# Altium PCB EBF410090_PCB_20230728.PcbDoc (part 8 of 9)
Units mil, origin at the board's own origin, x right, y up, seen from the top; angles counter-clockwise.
Board outline 5393.69 x 3858.26 mil, 6 copper layers (TOP, GND02, ART03, ART04, PWR05, BOTTOM), stack 47.2 mil thick; 570 components, 437 nets, 2015 pads, 1260 vias.
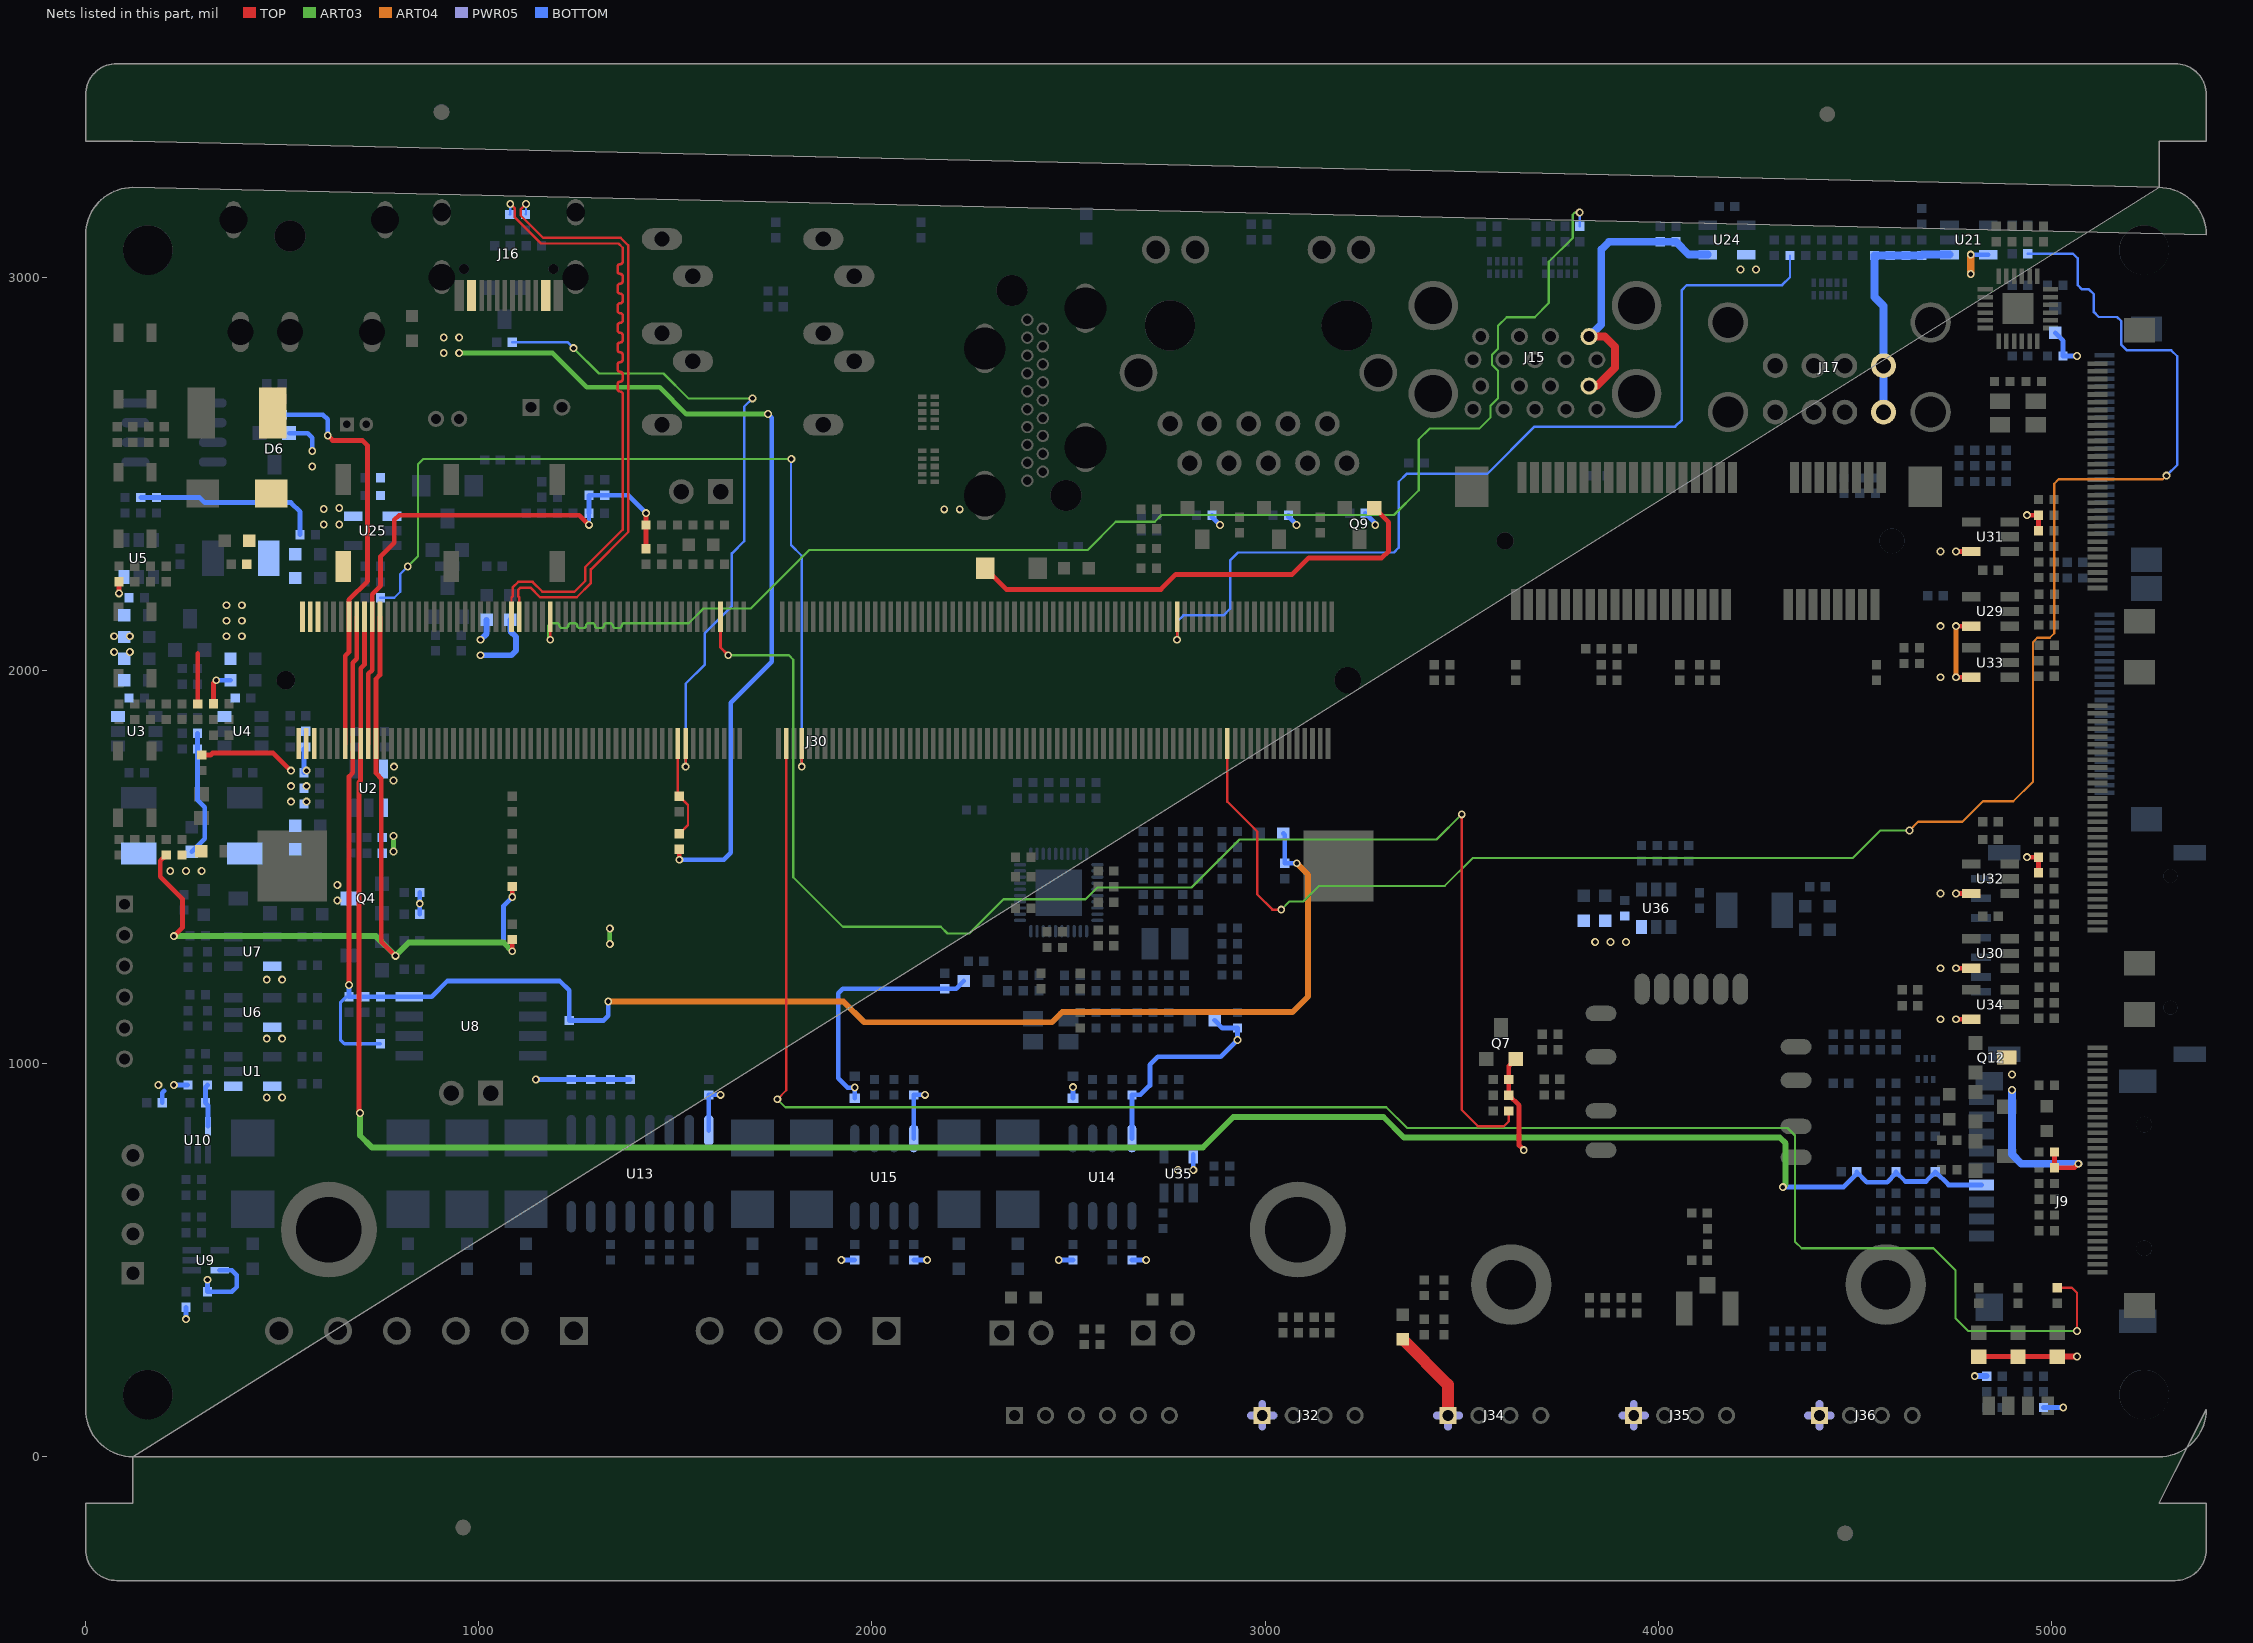
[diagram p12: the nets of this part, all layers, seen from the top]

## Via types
v1: diameter 20, hole 12, TOP to BOTTOM, 1260 vias

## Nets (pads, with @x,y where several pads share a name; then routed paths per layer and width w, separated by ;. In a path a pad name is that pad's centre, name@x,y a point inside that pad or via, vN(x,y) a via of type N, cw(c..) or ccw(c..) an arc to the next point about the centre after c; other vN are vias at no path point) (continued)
USB3_HOST1_SSTXP: C115.2 J30.195 | length 3556.1
  TOP w6.23: v1(1181.57,2078.07) J30.195@1181.57,2136.54
  ART03 w5.66: v1(1181.57,2078.07) 1176.4,2083.24 1176.4,2114.34 1182.06,2120 1198.89,2120 cw(c1198.89,2114) 1204.89,2114 ccw(c1210.89,2114) 1210.89,2108 1221.53,2108 ccw(c1221.53,2114) 1227.53,2114 cw(c1233.53,2114) 1233.53,2120 1244.17,2120 cw(c1244.17,2114) 1250.17,2114 ccw(c1256.17,2114) 1256.17,2108 1266.81,2108 ccw(c1266.81,2114) 1272.81,2114 cw(c1278.81,2114) 1278.81,2120 1289.45,2120 cw(c1289.45,2114) 1295.45,2114 ccw(c1301.45,2114) 1301.45,2108 1312.09,2108 ccw(c1312.09,2114) 1318.09,2114 cw(c1324.09,2114) 1324.09,2120 1334.73,2120 cw(c1334.73,2114) 1340.73,2114 ccw(c1346.73,2114) 1346.73,2108 1357.37,2108 ccw(c1357.37,2114) 1363.37,2114 cw(c1369.37,2114) 1369.37,2120 1533.99,2120 1571.33,2157.34 1691.33,2157.34 1839.99,2306 2548,2306 2620,2378 2719.01,2378 2736.35,2395.34 3327.66,2395.34 3390.66,2458.34 3390.66,2587.66 3418,2615 3545,2615 3573,2643 3573,2672.71 3592.64,2692.35 3592.64,2761.9 3577.05,2777.49 3577.05,2802.75 3592.64,2818.34 3592.64,2876.65 3614.33,2898.34 3685.66,2898.34 3721.66,2934.34 3721.66,3039.34 3782.33,3100.01 3782.33,3159.33 3788,3165 v1(3800,3165)
  BOTTOM w6.23: C115.2@3800,3129.68 v1(3800,3165)
USB20_HOST_PWR_EN: J30.28 R141.1 | length 4536.8
  TOP w6.16: J30.28@2904.02,1813.7 2904.02,1665.99 2980,1590.01 2980,1430 3018.42,1391.58 v1(3040.95,1391.58)
  ART03 w5.61: v1(3040.95,1391.58) 3061.37,1412 3097,1412 3137,1452 3457,1452 3528,1523 4495,1523 4565,1593 v1(4638.89,1593)
  ART04 w5.61: v1(4638.89,1593) 4660.89,1615 4774,1615 4826,1667 4903,1667 4953,1717 4953,2071.78 4964.22,2083 4995.78,2083 5007,2094.22 5007,2475 5018,2486 5283.56,2486 v1(5293,2495.44)
  BOTTOM w6.16: R141.1@4939.68,3060 5055,3060 5067,3048 5067,2980.16 5078.16,2969 5095.68,2969 5108,2956.68 5108,2911.32 5120.32,2899 5167,2899 5178,2888 5178,2828 5192,2814 5305,2814 5320,2799 5320,2522.44 v1(5293,2495.44)
USB20_OTG_PWR_EN: J30.138 R150.1 | length 2208
  TOP w6.16: v1(1821.34,1755.23) J30.138@1821.34,1813.7
  ART03 w5.61: v1(819.37,2264.37) 845,2290 845,2524 859,2538 v1(1795,2538)
  BOTTOM w6.16: R150.1@749.68,2185 785,2185 800,2200 800,2245 v1(819.37,2264.37) ; v1(1795,2538) 1794,2537 1794,2319 1821.34,2291.66 v1(1821.34,1755.23)
USB30_HOST_PWR_EN: J30.41 R147.1 | length 2445.4
  TOP w6.16: v1@2776.06,2078.09 J30.41@2776.06,2136.54
  BOTTOM w6.16: v1(2776.04,2078.07) 2776.04,2124.04 2792,2140 2894,2140 2911,2157 2911,2280 2931,2300 3327.68,2300 3340,2312.32 3340,2480 3360,2500 3565,2500 3685,2620 4042.68,2620 4060,2637.32 4060,2967.68 4072.32,2980 4315,2980 4335,3000 R147.1@4335,3055.32
"USB OTG": C125.1 C126.1 J16.A4 J16.A9 J16.B4 J16.B9 R149.1 U25.1 | length 2177.8
  TOP w12: v1(1510,1518.52) R149.1@1510,1545.32
  ART03 w12: v1(950,2807.26) 1187.74,2807.26 1275,2720 1460,2720 1528,2652 v1(1735.37,2652)
  BOTTOM w12: v1(1510,1518.52) 1623.52,1518.52 1641,1536 1641,1917.99 1745,2021.99 1745,2642.37 v1(1735.37,2652)
  other v1: 910.63,2807.26 910.63,2846.63 950,2846.63
USB_OTG0_DM: J30.203 R134.2 | length 1547.7
  TOP w6.23: J30.203@1102.83,2136.54 1102.83,2185.71 1100.1,2188.44 1100.1,2204.54 1106.33,2210.77 1131.11,2210.77 1155.88,2186 1248.99,2186 1285,2222.01 1285,2257.01 1380.23,2352.24 1380.23,3080.9 1361.02,3100.11 1163.89,3100.11 1106.11,3157.89 1106.11,3172.59 v1(1120,3186.48)
  BOTTOM w6.23: R134.2@1119,3159.68 1120,3160.68 v1(1120,3186.48)
USB_OTG0_DP: J30.205 R135.2 | length 1650.7
  TOP w6.23: v1(1080,3186.48) 1091.88,3174.6 1091.88,3151.99 1157.99,3085.88 1355.12,3085.88 1366,3075 1366,3039.89 cw(c1359.5,3039.89) 1359.5,3033.39 ccw(c1359.5,3026.89) 1353,3026.89 1353,3014.97 ccw(c1359.5,3014.97) 1359.5,3008.47 cw(c1359.5,3001.97) 1366,3001.97 1366,2990.05 cw(c1359.5,2990.05) 1359.5,2983.55 ccw(c1359.5,2977.05) 1353,2977.05 1353,2965.13 ccw(c1359.5,2965.13) 1359.5,2958.63 cw(c1359.5,2952.13) 1366,2952.13 1366,2940.21 cw(c1359.5,2940.21) 1359.5,2933.71 ccw(c1359.5,2927.21) 1353,2927.21 1353,2915.29 ccw(c1359.5,2915.29) 1359.5,2908.79 cw(c1359.5,2902.29) 1366,2902.29 1366,2890.37 cw(c1359.5,2890.37) 1359.5,2883.87 ccw(c1359.5,2877.37) 1353,2877.37 1353,2865.45 ccw(c1359.5,2865.45) 1359.5,2858.95 cw(c1359.5,2852.45) 1366,2852.45 1366,2840.53 cw(c1359.5,2840.53) 1359.5,2834.03 ccw(c1359.5,2827.53) 1353,2827.53 1353,2815.61 ccw(c1359.5,2815.61) 1359.5,2809.11 cw(c1359.5,2802.61) 1366,2802.61 1366,2790.69 cw(c1359.5,2790.69) 1359.5,2784.19 ccw(c1359.5,2777.69) 1353,2777.69 1353,2765.77 ccw(c1359.5,2765.77) 1359.5,2759.27 cw(c1359.5,2752.77) 1366,2752.77 1366,2740.85 cw(c1359.5,2740.85) 1359.5,2734.35 ccw(c1359.5,2727.85) 1353,2727.85 1353,2715.93 ccw(c1359.5,2715.93) 1359.5,2709.43 cw(c1359.5,2702.93) 1366,2702.93 1366,2358.14 1270.77,2262.91 1270.77,2227.91 1243.09,2200.23 1161.78,2200.23 1137.01,2225 1100.43,2225 1085.87,2210.44 1085.87,2188.44 1083.15,2185.72 J30.205@1083.15,2136.54
  BOTTOM w6.23: R135.2@1079,3159.68 1080,3160.68 v1(1080,3186.48)
USB_OTG0_ID: J30.160 R138.2 | length 1736.2
  TOP w6.16: v1(1526.05,1755.23) J30.160@1526.05,1813.7
  ART03 w5.61: v1(1241,2819.68) 1305.68,2755 1470,2755 1533,2692 v1(1696,2692)
  BOTTOM w6.16: R138.2@1084.68,2835 1225.68,2835 v1(1241,2819.68) ; v1(1526.05,1755.23) 1526.05,1966.05 1575,2015 1575,2095 1643.76,2163.76 1643.76,2297.76 1675,2329 1675,2671 v1(1696,2692)
USB_OTG0_VBUSDET: J30.162 R149.2 R151.1 | length 248.7
  TOP w6.16: J30.162@1506.37,1813.7 1506.37,1683.31 R151.1@1510,1679.68 1532,1657.68 1532,1606.68 R149.2@1510,1584.68
USER_LED: J30.142 R45.2 | length 4845.8
  TOP w6.16: v1(1759.37,909.37) 1781.97,931.97 J30.142@1781.97,1813.7 ; R45.2@5015,429.68 5052.32,429.68 5065,417 v1(5065,319.49)
  ART03 w5.61: v1(1759.37,909.37) 1779.74,889 3308.47,889 3361.47,836 4328.99,836 4348,816.99 4348,546.99 4364.99,530 4699.99,530 4756,473.99 4756,352.47 4788.98,319.49 v1(5065,319.49)
VCC3V3_SD: C54.1 C73.1 C74.1 J9.4 J30.243 J30.244 | length 5723.6
  TOP w12: v1(697.95,874.05) 695,877 695,1715 699.28,1719.28 J30.244@699.28,1813.7 700,1814.42 700,2005 709.13,2014.13 J30.243@709.13,2136.54
  ART03 w15: v1(697.95,874.05) 697.95,817.01 727.96,787 2842,787 2919,864 3301,864 3353,812 4309,812 4324,797 4324,692.74 v1(4316.89,685.63)
  BOTTOM w12: v1(4316.89,685.63) 4317.26,686 4471,686 4504.68,719.68 C54.1@4504.68,724.2 ; C54.1@4504.68,725 C54.1@4504.68,724.2 ; C73.1@4604.68,725 C73.1@4604.68,724.2 ; J9.4@4822.41,691.34 4738.34,691.34 C74.1@4704.68,725 4704.68,723.78 4680.9,700 4628.88,700 C73.1@4604.68,724.2 ; C54.1@4504.68,724.2 4530.88,698 4582,698 4604.68,720.68 C73.1@4604.68,724.2
VCC3V3_SYS: C8.1 C15.1 C16.1 C17.1 L1.2 R4.1 U1.5 U6.5 U31.5 U32.5 U35.5 | length 440.4
  TOP w12: v1(4757.19,1432.6) U32.5@4795.79,1432.6 ; v1(4757.19,2302.6) U31.5@4795.79,2302.6
  ART04 w12: v1(499.8,913.42) v1@500,913.22
  BOTTOM w12: C15.1@270,1538.5 303,1571.5 303,1652 284.68,1670.32 C8.1@284.68,1800 R4.1@284.68,1840 ; v1(2817.4,729.02) U35.5@2817.4,769.21
  other v1: 2778.03,729.02 460.43,913.42 460.43,1063.42 499.8,1063.42 4717.82,1432.6 215,1490 255,1490 295,1490 4717.82,2302.6
VCC5V0_SYS: C20.1 C24.1 C25.1 C26.1 C50.1 C51.1 J30.255 J30.256 J30.257 J30.258 J30.259 J30.260 L2.2 R11.1 R16.1 U2.5 U29.5 U30.5 U33.5 U34.5 | length 638.9
  TOP w12: R16.1@295,1784.68 317.8,1784.68 322.8,1789.68 477.44,1789.68 v1(522.12,1745) ; v1(4757.19,1112.6) U34.5@4795.79,1112.6 ; v1(4757.19,1242.6) U30.5@4795.79,1242.6 ; v1(4757.19,1982.6) U33.5@4795.79,1982.6 ; v1(4757.19,2112.6) U29.5@4795.79,2112.6
  ART04 w12: v1(4757.19,1982.6) v1(4757.19,2112.6)
  BOTTOM w12: C51.1@555.32,1740 555.32,1800.64 C20.1@559.68,1805 R11.1@559.68,1845
  other v1: 4717.82,1112.6 4717.82,1242.6 522.12,1666.26 561.49,1666.26 522.12,1705.63 561.49,1705.63 783.12,1720 561.49,1745 784.2,1755.23 4717.82,1982.6 4717.82,2112.6
VCC5V0_SYS_2: C29.1 C34.1 C35.1 C36.1 L3.2 R10.1 R20.1 U7.5 U21.5 U24.5 U25.5 | length 629.4
  ART04 w20: v1(4795,3008.23) v1(4795,3057.6)
  BOTTOM w12: R20.1@140,2439.68 C29.1@180,2439.68 290.32,2439.68 303,2427 522,2427 545.32,2403.68 C36.1@545.32,2345 ; v1(4795,3057.6) U21.5@4839.21,3057.6
  BOTTOM w15: v1(1004.41,2078.07) 1020,2093.66 R10.1@1020,2128.5
  other v1: 460.43,1213.42 499.8,1213.42 605.63,2371.15 645,2371.15 605.63,2410.52 645,2412.95 4209.37,3020 4248.74,3020
VCC5V0_USB20_HOST: C112.1 C113.1 C116.1 C117.1 J17.1 J17.7 U21.1 | length 599.5
  BOTTOM w20: J17.1@4572.9,2657.04 J17.7@4572.9,2775.15 4572.9,2927.1 4550,2950 C113.1@4550,3055.32 C112.1@4590,3055.32 C117.1@4630,3055.32 C116.1@4670,3055.32 4672.28,3057.6 U21.1@4740.79,3057.6
VCC5V0_USB30_HOST: C122.1 C123.1 J15.1 J15.10 U24.1 | length 741.7
  TOP w20: J15.10@3824.08,2723.19 3843.19,2723.19 3890,2770 3890,2823.14 3863.97,2849.17 J15.1@3824.08,2849.17
  BOTTOM w20: J15.1@3824.08,2849.17 3855,2880.09 3855,3070.32 3875,3090.32 C123.1@4005,3090.32 C122.1@4045,3090.32 4077.72,3057.6 U24.1@4125.79,3057.6
VCC_1V8: C52.1 C57.1 C58.1 C105.1 J30.245 J30.246 L7.2 R37.1 R38.1 U8.8 | length 4294.9
  TOP w12: v1(670,1200) 670,1730 679.6,1739.6 J30.246@679.6,1813.7 679.6,2019.6 689.45,2029.45 J30.245@689.45,2136.54
  ART04 w15: v1(1329.2,1157.93) 1927.07,1157.93 1980,1105 2458,1105 2484,1131 3070,1131 3109.5,1170.5 3109.5,1480.5 v1(3080.32,1509.68)
  BOTTOM w8: C52.1@670,1169.68 662.68,1169.68 648,1155 648,1060.32 658,1050.32 R38.1@750,1050.32
  BOTTOM w12: v1(670,1200) C52.1@670,1169.68 C57.1@710,1169.68 C58.1@750,1169.68 822.2,1169.68 U8.8@822.52,1170 880,1170 920,1210 1206,1210 1230,1186 R37.1@1230,1109.68 1317.19,1109.68 1329.2,1121.69 v1(1329.2,1157.93) ; L7.2@3046.5,1585 3050,1581.5 C105.1@3050,1509.68 v1(3080.32,1509.68)
VCC_12V: C1.1 C2.1 C3.1 C12.1 C13.1 C14.1 C21.1 C22.1 C23.1 C31.1 C32.1 C33.1 C38.1 C165.1 C170.1 C171.1 C172.1 D1.2 F1.2 Q4.3 Q12.3 R7.1 R9.1 R14.1 R23.1 R27.1 R196.1 U3.3 U4.3 U5.3 U36.3 | length 939.3
  TOP w12: v1(85,2196) R23.1@85,2225.32 ; R7.1@285,1914.68 285,2043 ; R14.1@325.32,1915 325.32,1968.24 v1(332.08,1975) ; C165.1@5007.68,775 R196.1@5007.68,735 5058.47,735 v1(5068.63,745.16)
  BOTTOM w12: v1(332.08,1975) C22.1@368.5,1975 ; R27.1@849.68,1380 v1(849.68,1406.8) C38.1@849.68,1435
  BOTTOM w15: v1(1004.41,2038.7) 1082.99,2038.7 1095,2050.71 1095,2085 1080,2100 R9.1@1080,2128.5
  BOTTOM w20: v1(4899.64,932.95) 4899.64,769.16 4923.64,745.16 v1(5068.63,745.16)
  other v1: 4899.64,972.32 3839.37,1309 3878.74,1309 3918.11,1309 640.23,1415.04 640.23,1454.41 72.37,2046.88 112.37,2046.88 72.37,2086.88 112.37,2086.88 357.96,2086.88 397.33,2086.88 357.96,2126.25 397.33,2126.25 357.96,2165.62 397.33,2165.62
VCC_RTC: J30.247 J30.248 R51.2 | length 1055.4
  TOP w12: v1(615.63,2597.37) 628,2585 704,2585 717,2572 717,2227 669.76,2179.76 J30.247@669.76,2136.54 669.76,2046.76 659.91,2036.91 J30.248@659.91,1813.7
  BOTTOM w12: R51.2@500,2650.32 603.62,2650.32 615.63,2638.31 v1(615.63,2597.37)
VCCA_1V8: C53.1 J30.239 J30.240 R35.1 R239.2 | length 2248.8
  TOP w12: R239.2@205,1530.32 190,1515.32 190,1475 246.21,1418.79 246.21,1346.05 v1(224.21,1324.05) ; J30.239@748.5,2136.54 748.5,1988.5 738.65,1978.65 J30.240@738.65,1813.7 738.65,1738.35 752,1725 752,1309.87 v1(787.87,1274) ; v1(1085,1285.85) C53.1@1085,1315.32 ; v1(1085,1423.52) R35.1@1085,1450.32
  ART03 w15: v1(224.21,1324.05) 737.82,1324.05 v1(787.87,1274) 821.87,1308 1062.85,1308 v1(1085,1285.85)
  BOTTOM w12: v1(1085,1285.85) 1063,1307.85 1063,1401.52 v1(1085,1423.52)
VCCIO_ACODEC: C55.1 C186.1 C191.1 J30.241 J30.242 R215.1 R217.1 | length 1436.8
  TOP w12: J30.242@718.97,1813.7 718.97,1990.97 728.82,2000.82 J30.241@728.82,2136.54 728.82,2193.82 750,2215 750,2290 785,2325 785,2383 797,2395 1255.32,2395 v1(1280,2370.32) ; R215.1@1425,2309.68 1425.32,2310 C186.1@1425.32,2370 v1(1425.32,2400)
  BOTTOM w10: v1(1280,2370.32) C55.1@1280,2400.32
  BOTTOM w12: C55.1@1280.32,2400 1280,2400.32 C191.1@1280,2445.32 R217.1@1320,2445.32 1380,2445.32 v1(1425.32,2400)
VDD_3V3: C5.1 C6.1 C59.1 C62.1 C69.1 C75.1 C76.1 C90.1 C94.1 C109.1 C127.1 C431.1 D6.2 D19.2 D20.2 J32.1 J34.1 J35.1 J36.1 L5.2 L6.2 LED1.2 LED2.2 LED3.2 Q7.2 R39.1 R42.1 R44.1 R47.2 R52.1 R53.1 R54.1 R55.1 R67.1 R68.1 R69.1 R70.1 R127.1 R152.1 R156.1 R157.1 R159.1 R164.1 R166.1 R168.1 R170.1 U1.1 U9.5 U10.5 U13.16 U14.8 U15.8 | length 3988.6
  TOP w12: Q7.2@3637.5,1011.5 3619.68,993.68 C109.1@3619.68,959.44 R127.1@3619.68,919.44 3620.26,919.44 3646,893.7 3646,791.72 v1(3657.89,779.83) ; LED3.2@4815,254.68 LED2.2@4915,254.68 LED1.2@5015,254.68 ; v1(4938,1525) R170.1@4967.32,1525 R166.1@4967.32,1485 ; v1(4938,2395) R168.1@4967.32,2395 R164.1@4967.32,2355
  TOP w15: LED1.2@5015,254.68 v1(5065,254.68)
  TOP w30: C431.1@3350,298.5 3465.08,183.42 J34.1@3465.08,105.01
  PWR05 w20: J32.1@2963.96,105.01 J32.1@2992.64,105.01 ; J32.1@2992.64,76.33 J32.1@2992.64,105.01 ; J32.1@2992.64,133.69 J32.1@2992.64,105.01 ; J32.1@3021.32,105.01 J32.1@2992.64,105.01 ; J34.1@3436.4,105.01 J34.1@3465.08,105.01 ; J34.1@3465.08,76.33 J34.1@3465.08,105.01 ; J34.1@3465.08,133.69 J34.1@3465.08,105.01 ; J34.1@3493.76,105.01 J34.1@3465.08,105.01 ; J35.1@3908.84,105.01 J35.1@3937.52,105.01 ; J35.1@3937.52,76.33 J35.1@3937.52,105.01 ; J35.1@3937.52,133.69 J35.1@3937.52,105.01 ; J35.1@3966.2,105.01 J35.1@3937.52,105.01 ; J36.1@4381.28,105.01 J36.1@4409.96,105.01 ; J36.1@4409.96,76.33 J36.1@4409.96,105.01 ; J36.1@4409.96,133.69 J36.1@4409.96,105.01 ; J36.1@4438.64,105.01 J36.1@4409.96,105.01
  BOTTOM w12: R42.1@194.68,900 194.68,925.46 199.61,930.39 ; v1(224.21,945.32) C6.1@260,945.32 ; v1(255,350) R39.1@255,380.32 ; v1(310,450) C59.1@310,419.68 372.09,419.68 384.09,431.68 384.09,462.09 372.09,474.09 U9.5@340.43,474.09 ; C5.1@310,945.32 304.68,940 C62.1@304.68,900 310.9,893.78 U10.5@310.9,840.43 ; D6.2@517.5,2603.5 564.26,2603.5 576.26,2591.5 v1(576.26,2558) ; v1(1145,959.68) R52.1@1235,959.68 R53.1@1285,959.68 R55.1@1335,959.68 R54.1@1385,959.68 ; U13.16@1584.8,829.8 1584.8,920.12 C69.1@1585,920.32 v1(1614.68,920.32) ; v1(1922.12,500.32) R68.1@1956.22,500.32 ; D20.2@1956.22,912.05 v1@1956.22,938.77 ; v1@1956.21,938.78 v1(1956.21,938.86) 1956.13,938.78 1938,938.78 1914,962.78 1914,1178.32 1926,1190.32 C94.1@2185,1190.32 2213.82,1190.32 L6.2@2233.5,1210 ; R70.1@2106.22,500.32 v1(2140.32,500.32) ; U15.8@2106.22,809.5 C76.1@2106.22,920.32 v1(2135,920.32) ; v1(2475,500.32) R67.1@2511.22,500.32 ; D19.2@2511.22,912.05 v1(2511.22,940) ; R69.1@2661.22,500.32 v1(2697.44,500.32) ; U14.8@2661.22,809.5 C75.1@2661.22,920.32 2683,920.32 2707,944.32 2707,997 2727,1017 2887,1017 v1(2930,1060) C90.1@2930,1090.32 2891.18,1090.32 L5.2@2871.5,1110 ; R159.1@2864.68,2395 2864.68,2390.32 v1(2885,2370) ; R157.1@3059.68,2395 3059.68,2390.32 v1(3080,2370) ; R156.1@3254.68,2400 3280,2374.68 v1(3280,2370) ; R44.1@4979.68,125 v1(5030,125) ; R152.1@5010,2858.5 5029.68,2838.82 C127.1@5029.68,2800 v1(5065,2800)
  BOTTOM w15: v1(4805,205) R47.2@4835.32,205
  other v1: 184.84,945.32 576.26,2518.63
VDD_5V: C10.1 C11.1 D27.2 Q9.1 U2.1 | length 1332.2
  TOP w12: D27.2@2288.07,2260 2342.07,2206 2735,2206 2773,2244 3069,2244 3111.02,2286.02 3297.02,2286.02 3314,2303 3314,2377 Q9.1@3277.5,2413.5
  ART03 w12: v1(782.71,1539.37) v1(782.71,1578.74) ; v1(1333.26,1304.37) v1(1333.26,1343.74)
  ART04 w12: v1(1333.26,1304.37) v1(1333.26,1343.74)
  other v1: 2184,2409.63 2223.37,2409.63
WLAN_PWR_EN: J30.151 R128.1 | length 3634.8
  TOP w6.16: v1(3500,1633.92) 3500,881.84 3541.16,840.68 3607.36,840.68 3619.68,853 R128.1@3619.68,879.44
  TOP w7.03: J30.151@1614.65,2136.54 1614.65,2058.38 v1(1634.33,2038.7)
  ART03 w5.61: v1(1634.33,2038.7) 1788.78,2038.7 1800,2027.48 1800,1474 1925.97,1348.03 2174.97,1348.03 2192,1331 2247.23,1331 2334.42,1418.19 2543.19,1418.19 2573,1448 2813,1448 2935,1570 3436.08,1570 v1(3500,1633.92)
pads on no net: H1.1 H2.1 H3.1 H4.1 J1. J6.1 J9. J14. J15.14 J15.15 J15.17 J15.18 J16. J16.A8 J16.B8 J20.13 J20.14 J21.13 J21.14 J21.16 J21.17 J21.18 J21.19 J21.20 J21.21 J22.1 J22.14 J22.24 J22.25 J22.30 J24. J24.3 J24.5 J24.6 J24.16 J24.17 J24.19 J24.28 J24.30 J24.32 J24.42 J24.44 J24.45 J24.46 J24.47 J24.48 J24.49 J24.51 J30. J30.19 J30.21 J30.27 J30.29 J30.32 J30.51 J30.65 J30.67 J30.69 J30.71 J30.73 J30.75 J30.96 J30.153 J30.213 J30.215 J30.217 J30.219 MARK.1 U12.1 U12.2 U17.3 U17.4 U17.9 U17.10 U17.11 U17.12 U17.13 U17.14 U22.2 U22.13 U22.17 U22.19 U22.21 U22.22 U22.23 U22.24 U26. U26.14 U37. U37.4 U37.6 U38.3

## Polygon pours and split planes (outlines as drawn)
GND on ART04 "ART04-GND" (solid, pour order 107): 82 vertices, not listed, extent 3318,1765 4067,2601
VCC_12V on ART04 "ART04-VCC_12V" (solid, pour order 109): 51 vertices, not listed, extent 348,691 4936,2300
VCC5V0_SYS_2 on ART04 "ART04-VCC5V0_SYS_2" (solid, pour order 110): 80 vertices, not listed, extent 180,1009 4816,3037
VDD_5V on ART04 "ART04-VDD_5V" (solid, pour order 104): 1273,1281 1260,1294 1260,2555 1270,2565 2220,2565 2235,2550 2235,2397 2210,2372 1423,2372 1403,2352 1403,1300 1384,1281 1273,1281
VCC3V3_SYS on ART04 "ART04-VCC3V3_SYS" (solid, pour order 111): 65 vertices, not listed, extent 180,397 5117,2400
GND on ART04 "ART04-GND 1" (solid, pour order 105): 82 vertices, not listed, extent 1423,1285 1894,2353
GND on ART04 "ART04-GND 2" (solid, pour order 117): 84 vertices, not listed, extent 20.01,20.01 5373.68,3208.33
VCC5V0_SYS on ART04 "ART04-VCC5V0_SYS" (solid, pour order 108): 50 vertices, not listed, extent 514,876 4776,2131
3V3_EDP on ART04 "ART04-3V3_EDP" (solid, pour order 106): 23 vertices, not listed, extent 2261,122 5241,707
GND on BOTTOM "BOTTOM-GND" (solid, pour order 74): 409,1918 409,2046 425,2062 425,2130 425,2132 430,2137 517,2137 525,2129 525,1926 517,1918 409,1918
GND on BOTTOM "BOTTOM-GND 1" (solid, pour order 84): 572,2358 572,2207 560,2195 436,2195 425,2184 425,2113 431,2107 631,2107 640,2116 640,2349 631,2358 572,2358
N28501 on BOTTOM "BOTTOM-N28501" (solid, pour order 13): 159,2350 253,2350 259,2344 259,2302 255,2298 225,2298 221,2302 221,2311 217,2315 159,2315 159,2350
N17592125 on BOTTOM "BOTTOM-N17592125" (solid, pour order 4): 4019,1460 4111,1460 4117,1454 4117,1423 4021,1423 4019,1425 4019,1460
"USB OTG" on BOTTOM "BOTTOM-USB OTG" (solid, pour order 90): 17 vertices, not listed, extent 738,2381 960,2857
GND on BOTTOM "BOTTOM-GND 2" (solid, pour order 78): 82 vertices, not listed, extent 4862,434 4958,713
GND on BOTTOM "BOTTOM-GND 3" (solid, pour order 67): 82 vertices, not listed, extent 1001,2434 1158,2548
GND on BOTTOM "BOTTOM-GND 4" (solid, pour order 68): 82 vertices, not listed, extent 276,1707 374,1892
5V0_CAM_1 on BOTTOM "BOTTOM-5V0_CAM_1" (solid, pour order 34): 5160,2394 5160,2341 5153,2334 5032,2334 5025,2341 5025,2388 5032,2395 5159,2395 5160,2394
GND on BOTTOM "BOTTOM-GND 5" (solid, pour order 102): 70 vertices, not listed, extent 4391,1274 4723,1986
GND on BOTTOM "BOTTOM-GND 6" (solid, pour order 82): 115 vertices, not listed, extent 485,2430 722,2573
VCC5V0_SYS_2 on BOTTOM "BOTTOM-VCC5V0_SYS_2" (solid, pour order 85): 19 vertices, not listed, extent 437,2219 704,2422
1V05_PHY on BOTTOM "BOTTOM-1V05_PHY" (solid, pour order 43): 2663,1213 2809,1213 2814,1218 2814,1338 2807,1345 2761,1345 2761,1251 2754,1244 2669,1244 2663,1238 2663,1213
GND on BOTTOM "BOTTOM-GND 7" (solid, pour order 75): 5003,2995 5003,2788 4927,2788 4927,2853 4915,2865 4868,2865 4861,2872 4861,2972 4884,2995 5003,2995
GND on BOTTOM "BOTTOM-GND 8" (solid, pour order 65): 82 vertices, not listed, extent 360,760 490,890
VCC_12V on BOTTOM "BOTTOM-VCC_12V" (solid, pour order 63): 82 vertices, not listed, extent 3793,1298 3972,1389
GND on BOTTOM "BOTTOM-GND 9" (solid, pour order 45): 82 vertices, not listed, extent 3785,1399 3932,1475
VCC5V0_SYS on BOTTOM "BOTTOM-VCC5V0_SYS" (solid, pour order 72): 358,1507 558,1507 568,1517 568,1747 558,1757 516,1757 506,1747 506,1572 496,1562 358,1562 358,1507
N17423580 on BOTTOM "BOTTOM-N17423580" (solid, pour order 49): 21 vertices, not listed, extent 335,1649 450,1860
3V3_EDP on BOTTOM "BOTTOM-3V3_EDP" (solid, pour order 79): 2805,705 2805,645 2885,645 2895,635 2895,360 2900,355 2950,355 2955,360 2955,700 2945,710 2810,710 2805,705
VCC_12V on BOTTOM "BOTTOM-VCC_12V 1" (solid, pour order 17): 82 vertices, not listed, extent 630,1400 700,1465
VDD_3V3 on BOTTOM "BOTTOM-VDD_3V3" (solid, pour order 30): 500,2622 579,2622 586,2615 586,2516 579,2509 544,2509 537,2516 537,2574 525,2586 500,2586 500,2622
5V0_CAM_2 on BOTTOM "BOTTOM-5V0_CAM_2" (solid, pour order 87): 5110,1734 5110,1160 5094,1144 5034,1144 5024,1134 5024,1107 5034,1097 5134,1097 5161,1124 5161,1734 5110,1734
GND on BOTTOM "BOTTOM-GND 10" (solid, pour order 44): 287,1588 287,1644 275,1656 275,1766 268,1773 199,1773 197,1771 197,1717 209,1705 228,1705 231,1702 231,1594 237,1588 287,1588
VCC5V0_SYS_2 on BOTTOM "BOTTOM-VCC5V0_SYS_2 1" (solid, pour order 15): 82 vertices, not listed, extent 445,1200 515,1265
GND on BOTTOM "BOTTOM-GND 11" (solid, pour order 66): 578,1519 578,1747 588,1757 642,1757 651,1748 651,1523 647,1519 578,1519
GND on BOTTOM "BOTTOM-GND 12" (solid, pour order 113): 205 vertices, not listed, extent 20.01,20.01 5373.68,3208.33
GND on BOTTOM "BOTTOM-GND 13" (solid, pour order 60): 5171,2680 5171,2766 5161,2776 5064,2776 5047,2793 5047,2848 5064,2865 5154,2865 5170,2849 5170,2827 5210,2787 5210,2680 5202,2672 5179,2672 5171,2680
GND on BOTTOM "BOTTOM-GND 14" (solid, pour order 89): 82 vertices, not listed, extent 1625,755 1920,880
GND on BOTTOM "BOTTOM-GND 15" (solid, pour order 88): 82 vertices, not listed, extent 2150,755 2445,880
GND on BOTTOM "BOTTOM-GND 16" (solid, pour order 62): 82 vertices, not listed, extent 3960,1254 4095,1373
VCC3V3_SYS on BOTTOM "BOTTOM-VCC3V3_SYS" (solid, pour order 14): 82 vertices, not listed, extent 445,1045 515,1110
N17759502 on BOTTOM "BOTTOM-N17759502" (solid, pour order 52): 20 vertices, not listed, extent 312,2453 498,2549
N03641 on BOTTOM "BOTTOM-N03641" (solid, pour order 48): 21 vertices, not listed, extent 65,1649 180,1860
VCC_12V on BOTTOM "BOTTOM-VCC_12V 2" (solid, pour order 59): 335,1869 385,1869 392,1876 392,2062 407,2077 407,2131 408,2132 408,2172 403,2177 355,2177 348,2170 348,2131 348,1909 335,1896 335,1869
N28533 on BOTTOM "BOTTOM-N28533" (solid, pour order 53): 21 vertices, not listed, extent 121,2220 351,2330
VDD_5V on BOTTOM "BOTTOM-VDD_5V" (solid, pour order 35): 82 vertices, not listed, extent 741,1517 793,1678
GND on BOTTOM "BOTTOM-GND 17" (solid, pour order 83): 18 vertices, not listed, extent 139,1917 256,2262
GND on BOTTOM "BOTTOM-GND 18" (solid, pour order 64): 82 vertices, not listed, extent 2510,2230 2670,2335
N17423559 on BOTTOM "BOTTOM-N17423559" (solid, pour order 5): 465,1734 465,1822 430,1822 430,1767 430,1755 427,1752 413,1752 413,1728 459,1728 465,1734
GND on BOTTOM "BOTTOM-GND 19" (solid, pour order 32): 82 vertices, not listed, extent 2840,718 2939,798
VDD_3V3 on BOTTOM "BOTTOM-VDD_3V3 1" (solid, pour order 40): 82 vertices, not listed, extent 175,920 405,960
GND on BOTTOM "BOTTOM-GND 20" (solid, pour order 20): 82 vertices, not listed, extent 811,2418 873,2500
MINIPCIE_3V3 on BOTTOM "BOTTOM-MINIPCIE_3V3" (solid, pour order 96): 21 vertices, not listed, extent 4288,1325 4397,1954
N17592129 on BOTTOM "BOTTOM-N17592129" (solid, pour order 56): 17 vertices, not listed, extent 3981,1330 4201,1435
VCC3V3_SYS on BOTTOM "BOTTOM-VCC3V3_SYS 1" (solid, pour order 22): 82 vertices, not listed, extent 2766,718 2834,798
VCC5V0_SYS on BOTTOM "BOTTOM-VCC5V0_SYS 1" (solid, pour order 3): 82 vertices, not listed, extent 742,1709 795,1776
GND on BOTTOM "BOTTOM-GND 21" (solid, pour order 86): 82 vertices, not listed, extent 2725,512 2910,694
GND on BOTTOM "BOTTOM-GND 22" (solid, pour order 73): 82 vertices, not listed, extent 4783,923 4949,1066
N17466585 on BOTTOM "BOTTOM-N17466585" (solid, pour order 36): 2730,1346 2623,1346 2604,1365 2595,1365 2595,1308 2602,1301 2669,1301 2675,1295 2675,1272 2682,1265 2730,1265 2730,1346
HDMI_5V on BOTTOM "BOTTOM-HDMI_5V" (solid, pour order 55): 2423,2230 2490,2230 2498,2238 2498,2382 2459,2421 2425,2421 2415,2411 2415,2238 2423,2230
VCC_12V on BOTTOM "BOTTOM-VCC_12V 3" (solid, pour order 71): 65,1869 101,1869 101,1911 108,1918 121,1918 122,1918 122,2201 111,2212 111,2255 66,2255 57,2246 57,1877 65,1869
GND on BOTTOM "BOTTOM-GND 23" (solid, pour order 24): 82 vertices, not listed, extent 730,2335 872,2375
GND on BOTTOM "BOTTOM-GND 24" (solid, pour order 94): 82 vertices, not listed, extent 745,763 1193,884
N03633 on BOTTOM "BOTTOM-N03633" (solid, pour order 6): 195,1734 195,1822 160,1822 160,1767 160,1755 157,1752 138,1752 138,1728 189,1728 195,1734
VCC5V0_SYS_2 on BOTTOM "BOTTOM-VCC5V0_SYS_2 2" (solid, pour order 16): 82 vertices, not listed, extent 4195,3005 4260,3075
VCC3V3_SYS on BOTTOM "BOTTOM-VCC3V3_SYS 2" (solid, pour order 69): 90,1563 297,1563 310,1550 310,1480 307,1477 99,1477 90,1486 90,1563
VCC3V3_SYS on BOTTOM "BOTTOM-VCC3V3_SYS 3" (solid, pour order 18): 82 vertices, not listed, extent 445,895 515,960
VCC5V0_SYS_2 on BOTTOM "BOTTOM-VCC5V0_SYS_2 3" (solid, pour order 25): 82 vertices, not listed, extent 4784,2997 4864,3073
3V3_AVDD_PHY on BOTTOM "BOTTOM-3V3_AVDD_PHY" (solid, pour order 23): 2273,1272 2351,1272 2357,1266 2357,1213 2320,1213 2312,1205 2312,1194 2280,1194 2280,1238 2273,1245 2273,1272
GND on BOTTOM "BOTTOM-GND 25" (solid, pour order 33): 82 vertices, not listed, extent 5022,2113 5102,2216
12V_EDP on TOP "TOP-12V_EDP" (solid, pour order 47): 4861,872 5030,872 5039,881 5039,1020 5032,1027 5001,1027 4994,1020 4994,925 4978,909 4861,909 4861,872
5V0_CAM_2 on TOP "TOP-5V0_CAM_2" (solid, pour order 31): 82 vertices, not listed, extent 4868,1094 5086,1128
HDMI_5V on TOP "TOP-HDMI_5V" (solid, pour order 41): 82 vertices, not listed, extent 2395,2220 2510,2300
GND on TOP "TOP-GND" (solid, pour order 114): 161 vertices, not listed, extent 20.01,20.01 5373.68,3208.33
N02088 on TOP "TOP-N02088" (solid, pour order 92): 248,2587 248,2893 267,2912 403,2912 421,2894 421,2776 403,2758 354,2758 339,2743 339,2589 339,2587 330,2578 257,2578 248,2587
VCC3V3_SYS on TOP "TOP-VCC3V3_SYS" (solid, pour order 29): 205,1505 205,1485 210,1480 305,1480 310,1485 310,1560 275,1560 260,1545 230,1545 225,1540 225,1515 220,1510 210,1510 205,1505
GND on TOP "TOP-GND 1" (solid, pour order 46): 82 vertices, not listed, extent 2530,2230 2695,2300
VCC3V3_SYS on TOP "TOP-VCC3V3_SYS 1" (solid, pour order 8): 82 vertices, not listed, extent 4705,2284 4825,2318
GND on TOP "TOP-GND 2" (solid, pour order 26): 82 vertices, not listed, extent 2581,1774 2638,1888
GND on TOP "TOP-GND 3" (solid, pour order 42): 82 vertices, not listed, extent 4945,793 5080,866
GND on TOP "TOP-GND 4" (solid, pour order 100): 4025,890 4025,350 4041,334 4213,334 4230,351 4230,700 4245,715 4430,715 4445,730 4445,910 4045,910 4025,890
VCC_12V on TOP "TOP-VCC_12V" (solid, pour order 28): 82 vertices, not listed, extent 4857,921 4915,1036
VCC5V0_SYS on TOP "TOP-VCC5V0_SYS" (solid, pour order 7): 82 vertices, not listed, extent 4705,1094 4825,1128
GND on TOP "TOP-GND 5" (solid, pour order 81): 22 vertices, not listed, extent 575,1695 656,2215
GND on TOP "TOP-GND 6" (solid, pour order 103): 62 vertices, not listed, extent 4384,1585 5150,2391
GND on TOP "TOP-GND 7" (solid, pour order 91): 2587,1502 2587,1125 2581,1119 2483,1119 2470,1132 2470,1349 2506,1385 2506,1516 2513,1523 2566,1523 2587,1502
GND on TOP "TOP-GND 8" (solid, pour order 50): 82 vertices, not listed, extent 604,2441 705,2568
GND on TOP "TOP-GND 9" (solid, pour order 70): 49 vertices, not listed, extent 1188,2791 1313,2990
VCC3V3_SYS on TOP "TOP-VCC3V3_SYS 2" (solid, pour order 9): 82 vertices, not listed, extent 4705,1414 4825,1448
GND on TOP "TOP-GND 10" (solid, pour order 95): 250,2525 393,2525 408,2510 408,2412 382,2386 382,2258 315,2258 309,2264 309,2300 294,2315 156,2315 154,2317 154,2518 161,2525 250,2525
VCC5V0_SYS on TOP "TOP-VCC5V0_SYS 1" (solid, pour order 80): 518,1656 566,1656 572,1662 572,1754 587,1769 587,2078 597,2088 597,2176 540,2176 540,1960 534,1954 534,1789 512,1767 512,1662 518,1656
GND on TOP "TOP-GND 11" (solid, pour order 58): 2387,1539 2476,1539 2486,1529 2486,1392 2476,1382 2388,1382 2387,1383 2387,1539
GND on TOP "TOP-GND 12" (solid, pour order 61): 193,1592 193,1806 201,1814 251,1814 260,1805 260,1560 255,1555 235,1555 230,1560 230,1585 225,1590 195,1590 193,1592
3V3_IMAGE_2 on TOP "TOP-3V3_IMAGE_2" (solid, pour order 38): 5143,1392 4883,1392 4871,1404 4871,1445 4918,1445 4918,1426 4926,1418 5086,1418 5092,1424 5143,1424 5143,1392
GND on TOP "TOP-GND 13" (solid, pour order 97): 69 vertices, not listed, extent 2170,2098 3170,2280
VCC_12V on TOP "TOP-VCC_12V 1" (solid, pour order 99): 27 vertices, not listed, extent 63,2037 674,2733
VCC5V0_SYS on TOP "TOP-VCC5V0_SYS 2" (solid, pour order 12): 82 vertices, not listed, extent 4710,1964 4830,1998
VCC5V0_SYS on TOP "TOP-VCC5V0_SYS 3" (solid, pour order 10): 82 vertices, not listed, extent 4705,2094 4825,2128
3V3_IMAGE_1 on TOP "TOP-3V3_IMAGE_1" (solid, pour order 39): 5143,2263 4927,2263 4899,2291 4871,2291 4871,2315 4929,2315 4950,2294 5143,2294 5143,2263
5V0_IMAGE_2 on TOP "TOP-5V0_IMAGE_2" (solid, pour order 57): 5144,1385 5144,1238 5131,1225 4875,1225 4870,1230 4870,1254 4953,1254 4957,1258 5080,1258 5092,1270 5092,1385 5144,1385
GND on TOP "TOP-GND 14" (solid, pour order 1): 305,1885 305,1825 310,1820 335,1820 340,1825 340,1885 335,1890 310,1890 305,1885
"USB OTG" on TOP "TOP-USB OTG" (solid, pour order 77): 27 vertices, not listed, extent 900,2790 1182,2994
VCC5V0_SYS on TOP "TOP-VCC5V0_SYS 4" (solid, pour order 11): 82 vertices, not listed, extent 4705,1224 4825,1258
VDD_5V on TOP "TOP-VDD_5V" (solid, pour order 51): 20 vertices, not listed, extent 2173,2233 2312,2420
N18386455 on TOP "TOP-N18386455" (solid, pour order 21): 4824,960 4765,960 4756,951 4756,906 4724,906 4724,986 4733,995 4824,995 4824,960
GND on TOP "TOP-GND 15" (solid, pour order 19): 325,1560 325,1485 330,1480 380,1480 385,1485 385,1555 380,1560 325,1560
N17685851 on TOP "TOP-N17685851" (solid, pour order 2): 4724,843 4779,843 4787,835 4824,835 4824,874 4724,874 4724,843
GND on TOP "TOP-GND 16" (solid, pour order 37): 82 vertices, not listed, extent 2384,1773 2459,1887
5V0_IMAGE_1 on TOP "TOP-5V0_IMAGE_1" (solid, pour order 54): 5143,2255 5143,2109 5131,2097 4874,2097 4870,2101 4870,2125 4953,2125 4956,2128 5079,2128 5092,2141 5092,2255 5143,2255
GND on TOP "TOP-GND 17" (solid, pour order 101): 18 vertices, not listed, extent 4821,915 5198,1493
3V3_EDP on TOP "TOP-3V3_EDP" (solid, pour order 0): 82 vertices, not listed, extent 5172,681 5232,712
GND on TOP "TOP-GND 18" (solid, pour order 27): 82 vertices, not listed, extent 3670,985 3770,1050
5V0_CAM_1 on ART03 "ART03-5V0_CAM_1" (solid, pour order 76): 18 vertices, not listed, extent 4954,1982 5087,2357
VDD_5V on ART03 "ART03-VDD_5V" (solid, pour order 98): 774,1590 1344,1590 1356,1578 1356,1305 1347,1296 1290,1296 1279,1307 1279,1431 1260,1450 773,1450 762,1461 762,1578 774,1590
GND on ART03 "ART03-GND" (solid, pour order 93): 4044,640 4044,313 4206,313 4206,640 4044,640
GND on ART03 "ART03-GND 1" (solid, pour order 112): 130 vertices, not listed, extent 20.01,20.01 5373.68,3208.33
VDD_3V3 on PWR05 "PWR05-VDD_3V3" (solid, pour order 116): 82 vertices, not listed, extent 20.01,20.01 5373.68,3208.33
GND on GND02 "GND02-GND" (solid, pour order 115): 82 vertices, not listed, extent 20.01,20.01 5373.68,3208.33

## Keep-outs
GND02:
  region: 4145,630 4145,470 4155,470 4155,405 4095,405 4095,470 4105,470 4105,630 4145,630
Multi-Layer:
  region: 2677.18,2468.07 3288.68,2468.07 3289.55,2468.11 3290.42,2468.22 3291.27,2468.41 3292.1,2468.67 3292.91,2469.01 3293.68,2469.41 3294.42,2469.88 3295.11,2470.41 3295.75,2471 3296.34,2471.64 3296.87,2472.33 3297.34,2473.07 3297.74,2473.84 3298.08,2474.65 3298.34,2475.48 3298.53,2476.33 3298.64,2477.2 3298.68,2478.07 3298.68,3120 2667.18,3120 2667.18,2478.07 2667.22,2477.2 2667.33,2476.33 2667.52,2475.48 2667.78,2474.65 2668.12,2473.84 2668.52,2473.07 2668.99,2472.33 2669.52,2471.64 2670.11,2471 2670.75,2470.41 2671.44,2469.88 2672.18,2469.41 2672.95,2469.01 2673.76,2468.67 2674.59,2468.41 2675.44,2468.22 2676.31,2468.11 2677.18,2468.07

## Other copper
TOP:
  region net MIC_INP: 1511.46,2496.01 1492.74,2477.27 1515,2453.75 1537.26,2477.27 1518.54,2496.01 1518.22,2496.31 1517.87,2496.57 1517.51,2496.81 1517.12,2497.01 1516.71,2497.18 1516.3,2497.31 1515.87,2497.4 1515.44,2497.46 1515,2497.48 1514.56,2497.46 1514.13,2497.4 1513.7,2497.31 1513.29,2497.18 1512.88,2497.01 1512.49,2496.81 1512.13,2496.57 1511.78,2496.31 1511.46,2496.01
  region net N18495099: 4092.82,133.46 4079.7,120.32 4095,104.24 4110.3,120.32 4097.18,133.46 4096.98,133.64 4096.77,133.8 4096.54,133.95 4096.3,134.07 4096.05,134.17 4095.8,134.26 4095.53,134.31 4095.27,134.35 4095,134.36 4094.73,134.35 4094.47,134.31 4094.2,134.26 4093.95,134.17 4093.7,134.07 4093.46,133.95 4093.23,133.8 4093.02,133.64 4092.82,133.46
  region net RS485_1_A: 2686.95,373.96 2659.42,346.48 2690,313.75 2720.58,346.48 2693.05,373.96 2692.69,374.21 2692.32,374.43 2691.92,374.62 2691.51,374.77 2691.09,374.88 2690.66,374.96 2690.23,374.99 2689.79,375 2689.36,374.96 2688.93,374.88 2688.51,374.77 2688.09,374.62 2687.7,374.44 2687.32,374.22 2686.96,373.97 2686.95,373.96
  pour cut-out: 5247,2516 5235,2516 5235,2551 5247,2551 5247,2516
  pour cut-out: 5309,2571 5296,2571 5296,2608 5309,2608 5309,2571
  pour cut-out: 5239,2641 5221,2641 5221,2670 5239,2670 5239,2641
  pour cut-out: 5242,2752 5229,2752 5229,2789 5242,2789 5242,2752
  pour cut-out: 178,2575 142,2575 142,2615 178,2615 178,2575
  region net N17701231: 2426.46,356.01 2407.74,337.27 2430,313.75 2452.26,337.27 2433.54,356.01 2433.22,356.31 2432.87,356.57 2432.51,356.81 2432.12,357.01 2431.71,357.18 2431.3,357.31 2430.87,357.4 2430.44,357.46 2430,357.48 2429.56,357.46 2429.13,357.4 2428.7,357.31 2428.29,357.18 2427.88,357.01 2427.49,356.81 2427.13,356.57 2426.78,356.31 2426.46,356.01
  region net N18495011: 3128.46,123.58 3128.47,105.01 3150.66,104.47 3150.12,126.65 3131.54,126.66 3131.27,126.65 3131.01,126.61 3130.74,126.56 3130.49,126.47 3130.24,126.37 3130,126.25 3129.77,126.1 3129.56,125.94 3129.36,125.76 3129.18,125.56 3129.02,125.35 3128.87,125.12 3128.75,124.88 3128.65,124.63 3128.56,124.38 3128.51,124.11 3128.47,123.85 3128.46,123.58
  region net EDP_TP_RESET: 2538.78,126.66 2520.2,126.65 2519.66,104.47 2541.85,105.01 2541.86,123.58 2541.85,123.85 2541.81,124.11 2541.76,124.38 2541.67,124.63 2541.57,124.88 2541.45,125.12 2541.3,125.35 2541.14,125.56 2540.96,125.76 2540.76,125.94 2540.55,126.1 2540.32,126.25 2540.08,126.37 2539.83,126.47 2539.58,126.56 2539.31,126.61 2539.05,126.65 2538.78,126.66
  region net MIC_INN: 1616.16,2417.3 1622.51,2423.52 1615,2455.61 1607.49,2423.52 1613.84,2417.3 1614.03,2417.21 1614.23,2417.13 1614.44,2417.08 1614.65,2417.04 1614.86,2417.01 1615.07,2417.01 1615.28,2417.03 1615.49,2417.06 1615.7,2417.11 1615.9,2417.18 1616.09,2417.27 1616.16,2417.3
  region net RS485_2_A: 2327.31,363.21 2310.42,346.48 2330,313.75 2349.58,346.48 2332.69,363.21 2332.31,363.43 2331.92,363.62 2331.51,363.77 2331.09,363.88 2330.66,363.96 2330.22,363.99 2329.79,364 2329.35,363.96 2328.92,363.88 2328.5,363.77 2328.09,363.62 2327.7,363.44 2327.32,363.22 2327.31,363.21
  pour cut-out: 4155,405 4095,405 4095,470 4105,470 4105,630 4145,630 4145,470 4155,470 4155,405
  region net EDP_TP_INT: 2460.04,126.66 2441.46,126.65 2440.92,104.47 2463.11,105.01 2463.12,123.58 2463.11,123.85 2463.07,124.11 2463.02,124.38 2462.93,124.63 2462.83,124.88 2462.71,125.12 2462.56,125.35 2462.4,125.56 2462.22,125.76 2462.02,125.94 2461.81,126.1 2461.58,126.25 2461.34,126.37 2461.09,126.47 2460.84,126.56 2460.57,126.61 2460.31,126.65 2460.04,126.66
  pour cut-out: 4404,1642 4394,1642 4394,1678 4404,1678 4404,1642
  pour cut-out: 4480,1704 4467,1704 4467,1739 4480,1739 4480,1704
  pour cut-out: 4556,1765 4545,1765 4545,1801 4556,1801 4556,1765
  pour cut-out: 4482,1821 4469,1821 4469,1856 4482,1856 4482,1821
  pour cut-out: 4562,1883 4544,1883 4544,1918 4562,1918 4562,1883
  pour cut-out: 4820,2015 4780,2015 4780,2050 4820,2050 4820,2015
  pour cut-out: 4695,2025 4680,2025 4680,2050 4695,2050 4695,2025
  region net N18495097: 4014.08,133.46 4000.96,120.32 4016.26,104.24 4031.56,120.32 4018.44,133.46 4018.24,133.64 4018.03,133.8 4017.8,133.95 4017.56,134.07 4017.31,134.17 4017.06,134.26 4016.79,134.31 4016.53,134.35 4016.26,134.36 4015.99,134.35 4015.73,134.31 4015.46,134.26 4015.21,134.17 4014.96,134.07 4014.72,133.95 4014.49,133.8 4014.28,133.64 4014.08,133.46
  region net I2C4_SCL_M0: 2620.6,86.44 2620.59,105.01 2598.4,105.55 2598.94,83.37 2617.52,83.36 2617.79,83.37 2618.05,83.41 2618.32,83.46 2618.57,83.55 2618.82,83.65 2619.06,83.77 2619.29,83.92 2619.5,84.08 2619.7,84.26 2619.88,84.46 2620.04,84.67 2620.19,84.9 2620.31,85.14 2620.41,85.39 2620.5,85.64 2620.55,85.91 2620.59,86.17 2620.6,86.44
  region net MIC_INP: 1516.73,2417.72 1531.72,2432.73 1515,2455.61 1498.28,2432.73 1513.27,2417.72 1513.43,2417.57 1513.59,2417.44 1513.78,2417.33 1513.96,2417.23 1514.16,2417.15 1514.37,2417.08 1514.57,2417.04 1514.79,2417.01 1515,2417 1515.21,2417.01 1515.43,2417.04 1515.63,2417.08 1515.84,2417.15 1516.04,2417.23 1516.22,2417.33 1516.41,2417.44 1516.57,2417.57 1516.73,2417.72
  region net N15980269: 2771.56,366.77 2766.34,334.53 2790.32,313.79 2812.26,337.27 2780.04,369.51 2779.71,369.8 2779.37,370.07 2779,370.3 2778.61,370.5 2778.21,370.67 2777.79,370.8 2777.37,370.89 2776.94,370.95 2776.5,370.97 2776.06,370.95 2775.63,370.89 2775.21,370.8 2774.79,370.67 2774.39,370.5 2774,370.3 2773.63,370.07 2773.29,369.8 2772.96,369.51 2772.67,369.18 2772.4,368.84 2772.17,368.47 2771.97,368.08 2771.8,367.68 2771.67,367.26 2771.58,366.84 2771.56,366.77
  region net N18495009: 3082.5,146.76 3056.08,120.32 3071.13,104.28 3084.68,118.31 3084.68,144.58 3082.5,146.76
  region net I2C4_SDA_M0: 2696.26,126.66 2677.68,126.65 2677.14,104.47 2699.33,105.01 2699.34,123.58 2699.33,123.85 2699.29,124.11 2699.24,124.38 2699.15,124.63 2699.05,124.88 2698.93,125.12 2698.78,125.35 2698.62,125.56 2698.44,125.76 2698.24,125.94 2698.03,126.1 2697.8,126.25 2697.56,126.37 2697.31,126.47 2697.06,126.56 2696.79,126.61 2696.53,126.65 2696.26,126.66
  region net GND: 3329.68,2805.28 3287.85,2805.27 3286.79,2756.38 3335.67,2757.44 3335.68,2799.28 3335.66,2799.8 3335.59,2800.32 3335.48,2800.83 3335.32,2801.33 3335.12,2801.82 3334.88,2802.28 3334.59,2802.72 3334.28,2803.14 3333.92,2803.52 3333.54,2803.88 3333.12,2804.19 3332.68,2804.48 3332.22,2804.72 3331.73,2804.92 3331.23,2805.08 3330.72,2805.19 3330.2,2805.26 3329.68,2805.28
  region net N18494970: 3620.38,133.46 3607.26,120.32 3622.56,104.24 3637.86,120.32 3624.74,133.46 3624.54,133.64 3624.33,133.8 3624.1,133.95 3623.86,134.07 3623.61,134.17 3623.36,134.26 3623.09,134.31 3622.83,134.35 3622.56,134.36 3622.29,134.35 3622.03,134.31 3621.76,134.26 3621.51,134.17 3621.26,134.07 3621.02,133.95 3620.79,133.8 3620.58,133.64 3620.38,133.46
  region net N18494968: 3541.64,133.46 3528.52,120.32 3543.82,104.24 3559.12,120.32 3546,133.46 3545.8,133.64 3545.59,133.8 3545.36,133.95 3545.12,134.07 3544.87,134.17 3544.62,134.26 3544.35,134.31 3544.09,134.35 3543.82,134.36 3543.55,134.35 3543.29,134.31 3543.02,134.26 3542.77,134.17 3542.52,134.07 3542.28,133.95 3542.05,133.8 3541.84,133.64 3541.64,133.46
ART04:
  region net PHY1_LED2: 3208.32,3101.88 3208.33,3070.44 3244.47,3069.73 3243.76,3105.87 3212.32,3105.88 3211.97,3105.86 3211.63,3105.82 3211.28,3105.74 3210.95,3105.64 3210.63,3105.51 3210.32,3105.34 3210.03,3105.16 3209.75,3104.94 3209.49,3104.71 3209.26,3104.45 3209.04,3104.17 3208.86,3103.88 3208.69,3103.57 3208.56,3103.25 3208.46,3102.92 3208.38,3102.57 3208.34,3102.23 3208.32,3101.88
  region net MDIN3_PHY: 2806.56,2570.49 2785.87,2549.78 2808.13,2526.96 2830.39,2549.78 2809.7,2570.49 2809.56,2570.62 2809.4,2570.74 2809.24,2570.84 2809.07,2570.93 2808.89,2571.01 2808.7,2571.06 2808.52,2571.11 2808.32,2571.13 2808.13,2571.14 2807.94,2571.13 2807.74,2571.11 2807.56,2571.06 2807.37,2571.01 2807.19,2570.93 2807.02,2570.84 2806.86,2570.74 2806.7,2570.62 2806.56,2570.49
  region net MDIP3_PHY: 2815.16,2625.95 2835.87,2605.26 2858.68,2627.52 2835.87,2649.78 2815.16,2629.09 2815.03,2628.95 2814.91,2628.79 2814.81,2628.63 2814.72,2628.46 2814.64,2628.28 2814.59,2628.09 2814.54,2627.91 2814.52,2627.71 2814.51,2627.52 2814.52,2627.33 2814.54,2627.13 2814.59,2626.95 2814.64,2626.76 2814.72,2626.58 2814.81,2626.41 2814.91,2626.25 2815.03,2626.09 2815.16,2625.95
  region net MDIN0_PHY: 3106.56,2569.7 3086.66,2549.78 3108.13,2526.96 3129.6,2549.78 3109.7,2569.7 3109.56,2569.83 3109.4,2569.95 3109.24,2570.05 3109.07,2570.14 3108.89,2570.22 3108.7,2570.27 3108.52,2570.32 3108.32,2570.34 3108.13,2570.35 3107.94,2570.34 3107.74,2570.32 3107.56,2570.27 3107.37,2570.22 3107.19,2570.14 3107.02,2570.05 3106.86,2569.95 3106.7,2569.83 3106.56,2569.7
  region net MDIN2_PHY: 2955.85,2580.7 2980.39,2605.26 2958.18,2628.07 2935.61,2605.57 2952.45,2581.01 2952.57,2580.86 2952.7,2580.71 2952.84,2580.58 2952.99,2580.46 2953.15,2580.36 2953.33,2580.27 2953.5,2580.19 2953.69,2580.13 2953.88,2580.09 2954.07,2580.06 2954.26,2580.05 2954.46,2580.06 2954.65,2580.08 2954.84,2580.12 2955.02,2580.18 2955.2,2580.25 2955.37,2580.34 2955.54,2580.44 2955.69,2580.56 2955.84,2580.69 2955.85,2580.7
  pour cut-out: 3090,110 2270,110 2250,130 2250,375 2265,390 2585,390 2590,395 2590,550 2585,555 725,555 660,620 180,620 170,630 170,2560 185,2575 2230,2575 2250,2555 2250,2520 2260,2510 2515,2510 2530,2525 2530,2835 2528,2837 2528,3147 2562,3181 5132,3181 5141,3172 5141,3003 5162,2982 5242,2982 5244,2980 5244,2864 5193,2813 5002,2813 4976,2787 4976,2541 5011,2506 5341,2506 5341,1677 5343,1675 5343,1655 5336,1648 5148,1648 5127,1627 5127,740 5146,721 5230,721 5249,702 5249,275 5212,238 3136,238 3133,235 3115,235 3105,225 3105,125 3090,110
  region net PHY1_LED1: 2674.81,3067.61 2697.05,3045.39 2723.1,3070.44 2697.05,3095.49 2674.81,3073.27 2674.58,3073.01 2674.36,3072.73 2674.18,3072.44 2674.01,3072.13 2673.88,3071.81 2673.78,3071.48 2673.7,3071.13 2673.66,3070.79 2673.64,3070.44 2673.66,3070.09 2673.7,3069.75 2673.78,3069.4 2673.88,3069.07 2674.01,3068.75 2674.18,3068.44 2674.36,3068.15 2674.58,3067.87 2674.81,3067.61
  region net MDIN1_PHY: 2906.56,2570.49 2885.87,2549.78 2908.13,2526.96 2930.39,2549.78 2909.7,2570.49 2909.56,2570.62 2909.4,2570.74 2909.24,2570.84 2909.07,2570.93 2908.89,2571.01 2908.7,2571.06 2908.52,2571.11 2908.32,2571.13 2908.13,2571.14 2907.94,2571.13 2907.74,2571.11 2907.56,2571.06 2907.37,2571.01 2907.19,2570.93 2907.02,2570.84 2906.86,2570.74 2906.7,2570.62 2906.56,2570.49
  region net MDIP1_PHY: 3056.56,2670.49 3035.87,2649.78 3058.13,2626.96 3080.39,2649.78 3059.7,2670.49 3059.56,2670.62 3059.4,2670.74 3059.24,2670.84 3059.07,2670.93 3058.89,2671.01 3058.7,2671.06 3058.52,2671.11 3058.32,2671.13 3058.13,2671.14 3057.94,2671.13 3057.74,2671.11 3057.56,2671.06 3057.37,2671.01 3057.19,2670.93 3057.02,2670.84 3056.86,2670.74 3056.7,2670.62 3056.56,2670.49
  region net MDIP0_PHY: 3115.16,2625.95 3135.87,2605.26 3158.68,2627.52 3135.87,2649.78 3115.16,2629.09 3115.03,2628.95 3114.91,2628.79 3114.81,2628.63 3114.72,2628.46 3114.64,2628.28 3114.59,2628.09 3114.54,2627.91 3114.52,2627.71 3114.51,2627.52 3114.52,2627.33 3114.54,2627.13 3114.59,2626.95 3114.64,2626.76 3114.72,2626.58 3114.81,2626.41 3114.91,2626.25 3115.03,2626.09 3115.16,2625.95
  region net MDIP2_PHY: 3006.56,2570.49 2985.87,2549.78 3008.13,2526.96 3030.39,2549.78 3009.7,2570.49 3009.56,2570.62 3009.4,2570.74 3009.24,2570.84 3009.07,2570.93 3008.89,2571.01 3008.7,2571.06 3008.52,2571.11 3008.32,2571.13 3008.13,2571.14 3007.94,2571.13 3007.74,2571.11 3007.56,2571.06 3007.37,2571.01 3007.19,2570.93 3007.02,2570.84 3006.86,2570.74 3006.7,2570.62 3006.56,2570.49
